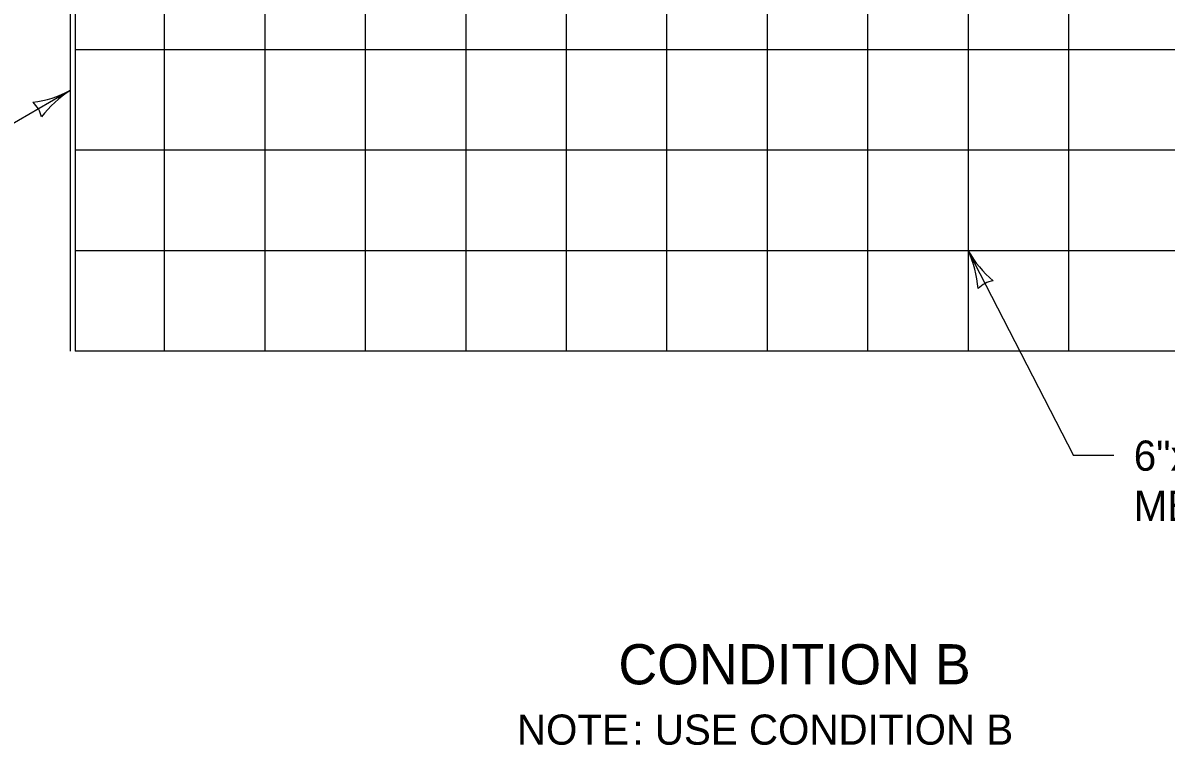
# Model space of a CAD drawing. Extents: x 49991.4 to 50021, y 49987.6 to 50011.4.
# Drawn here: x 50006.049 to 50008.325, y 49996.106 to 49997.543 of the extents above; entities that cross this region are included whole.
import ezdxf

# ---------------------------------------------------------------- set-up
doc = ezdxf.new("R2010")
doc.units = 0
for name, color, linetype in [('Level 1', 7, 'Continuous'), ('Level 2', 7, 'Continuous'), ('Level 3', 7, 'Continuous'), ('Level 4', 7, 'Continuous')]:
    doc.layers.add(name, color=color, linetype=linetype)

msp = doc.modelspace()

# ---------------------------------------------------------------- linework, layer by layer
at = {"layer": 'Level 1'}
for p, q in [((50006.1436, 49998.4848), (50006.1436, 49996.8898)), ((50006.153, 49997.6337), (50006.153, 49996.8898))]:
    msp.add_line(p, q, dxfattribs=at)
at = {"layer": 'Level 2'}
for p in [(50007.9305, 49997.0898), (50008.2202, 49996.6822)]:
    msp.add_line(p, (50008.1402, 49996.6822), dxfattribs=at)
at = {"layer": 'Level 3'}
msp.add_line((50006.1436, 49997.4086), (50005.8622, 49997.2461), dxfattribs=at)
for centre, radius, start, end in [((50006.0405, 49997.6056), 0.2223, 277.456, 297.6395), ((50006.27, 49997.2128), 0.233, 122.8273, 142.0772), ((50006.0326, 49997.3445), 0.0548, 12.1388, 47.8612), ((50007.7288, 49996.9964), 0.2223, 4.6736, 24.8571), ((50008.1322, 49997.2065), 0.233, 210.0449, 229.2947), ((50007.9892, 49996.9758), 0.0548, 99.3564, 135.0787)]:
    msp.add_arc(centre, radius, start, end, dxfattribs=at)
at = {"layer": 'Level 4'}
for p, q in [((50007.1305, 49998.2898), (50007.1305, 49996.8898)), ((50007.3305, 49998.2898), (50007.3305, 49996.8898)), ((50007.5305, 49998.2898), (50007.5305, 49996.8898)), ((50007.7305, 49998.2898), (50007.7305, 49996.8898)), ((50007.9305, 49998.2898), (50007.9305, 49996.8898)), ((50008.1305, 49998.2898), (50008.1305, 49996.8898)), ((50006.3305, 49997.6337), (50006.3305, 49996.8898)), ((50006.5305, 49997.6337), (50006.5305, 49996.8898)), ((50006.7305, 49997.6337), (50006.7305, 49996.8898)), ((50006.9305, 49997.6337), (50006.9305, 49996.8898)), ((50009.0987, 49997.4898), (50006.153, 49997.4898)), ((50009.0987, 49997.2898), (50006.153, 49997.2898)), ((50009.0987, 49997.0898), (50006.153, 49997.0898)), ((50009.0987, 49996.8898), (50006.153, 49996.8898))]:
    msp.add_line(p, q, dxfattribs=at)

# ---------------------------------------------------------------- texts
at = {"layer": 'Level 2'}
for s, height, p in [('6"x6" [150x150]  GALVANIZED ', 0.06, (50008.2602, 49996.6522)), ('MESH REINFORCEMENT PANEL', 0.06, (50008.2602, 49996.5522)), ('CONDITION B', 0.08, (50007.2344, 49996.2271)), ('NOTE', 0.06, (50007.0325, 49996.1071)), (': USE CONDITION B', 0.06, (50007.2624, 49996.1071))]:
    msp.add_text(s, height=height, dxfattribs=at).set_placement(p)

doc.saveas('drawing.dxf')
